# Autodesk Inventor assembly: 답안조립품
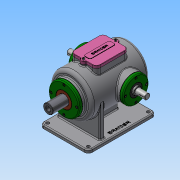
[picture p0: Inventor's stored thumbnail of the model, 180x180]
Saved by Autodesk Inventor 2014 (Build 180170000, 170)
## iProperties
Created: 2020-08
Part Number: 답안조립품
Document SubType Name: Assembly
Designer: net
Mass: 4945.07 g
Surface Area: 4564.63 cm^2
Volume: 2066.93 cm^3
Density: 2.39247 g/cm^3
Author: net
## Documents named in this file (15)
- C:\Users\net\Desktop\600806V1036\답안조립품.iam
- C:\Users\net\Desktop\600806V1036\본체.ipt
- C:\Users\net\Desktop\600806V1036\개스킷 B.ipt
- C:\Users\net\Desktop\600806V1036\개스킷 A.ipt
- C:\Users\net\Desktop\600806V1036\상부커버.ipt
- C:\Users\net\Desktop\600806V1036\베어링 6205.ipt
- 베어링 6205.ipt
- C:\Users\net\Desktop\600806V1036\축 커버.ipt
- C:\Users\net\Desktop\600806V1036\볼트 M4.ipt
- C:\Users\net\Desktop\600806V1036\슬라이드 커버.ipt
- C:\Users\net\Desktop\600806V1036\부시.ipt
- C:\Users\net\Desktop\600806V1036\오일 실 25 38 8.ipt
- C:\Users\net\Desktop\600806V1036\편심축.ipt
- C:\Users\net\Desktop\600806V1036\슬라이드.ipt
- C:\Users\net\Desktop\600806V1036\가변스프링.ipt
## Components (4 placed, 3 different names)
1. 개스킷 B:1
2. 개스킷 B:2
3. 개스킷 A:1
4. 가변스프링:1
